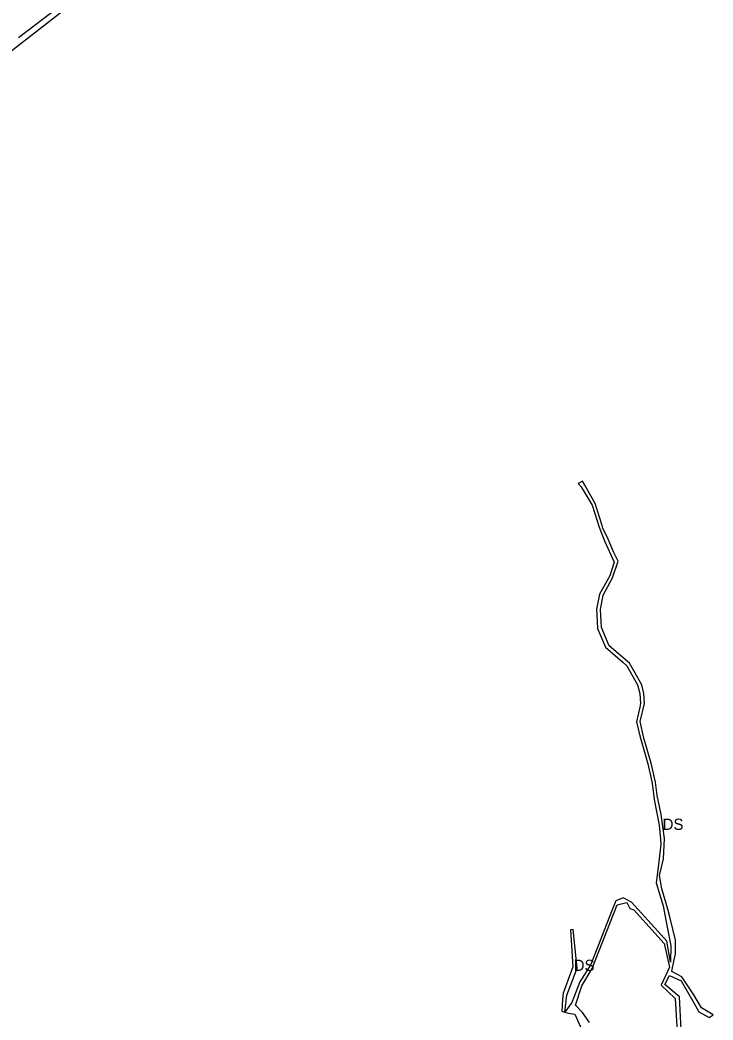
# Model space of a CAD drawing. Extents: x -477304 to -465641, y -1159113 to -1149285.
# Drawn here: x -474568 to -474013, y -1153742 to -1152941 of the extents above; entities that cross this region are included whole.
import ezdxf

# ---------------------------------------------------------------- set-up
doc = ezdxf.new("R2010")
doc.units = 0
doc.layers.add('35', color=7, linetype='Continuous')

msp = doc.modelspace()

# ---------------------------------------------------------------- linework, layer by layer
at = {"layer": '35'}
for p, q in [((-474117.21, -1153310.37), (-474120.55, -1153312.29)), ((-474120.55, -1153312.29), (-474118.33, -1153314.98)), ((-474118.33, -1153314.98), (-474109.34, -1153329.58)), ((-474115.45, -1153313.46), (-474117.21, -1153310.37)), ((-474107.08, -1153328.22), (-474115.45, -1153313.46)), ((-474109.34, -1153329.58), (-474103.95, -1153347.13)), ((-474101.48, -1153345.97), (-474107.08, -1153328.22)), ((-474103.95, -1153347.13), (-474099.47, -1153358.02)), ((-474100.84, -1153347.88), (-474101.48, -1153345.97)), ((-474096.77, -1153356.84), (-474100.84, -1153347.88)), ((-474092.37, -1153366.84), (-474096.77, -1153356.84)), ((-474088.52, -1153374.34), (-474092.37, -1153366.84)), ((-474103.66, -1153400.74), (-474106.05, -1153412.9)), ((-474102.89, -1153413.22), (-474100.52, -1153401.64)), ((-474106.05, -1153412.9), (-474105.79, -1153417.38)), ((-474101.96, -1153427.64), (-474102.89, -1153413.22)), ((-474085.02, -1153455.26), (-474081.66, -1153458.19)), ((-474067.44, -1153488.28), (-474067.98, -1153480.47)), ((-474070.9, -1153502.68), (-474067.44, -1153488.28)), ((-474068.12, -1153516.14), (-474070.9, -1153502.68)), ((-474062.31, -1153536.14), (-474068.12, -1153516.14)), ((-474058.76, -1153551.41), (-474062.31, -1153536.14)), ((-474061.5, -1153552.16), (-474059.87, -1153565.08)), ((-474052.35, -1153612.75), (-474051.54, -1153596.47)), ((-474055.51, -1153625.93), (-474052.35, -1153612.75)), ((-474053.57, -1153636.74), (-474055.51, -1153625.93)), ((-474090.58, -1153646.36), (-474093.46, -1153653.42)), ((-474079.23, -1153652.59), (-474076.22, -1153653.53)), ((-474054.16, -1153673.41), (-474078.06, -1153647.3)), ((-474124.63, -1153669.37), (-474126.72, -1153669.59)), ((-474126.72, -1153669.59), (-474125.01, -1153699.24)), ((-474049.73, -1153678.55), (-474054.16, -1153673.41)), ((-474046.8, -1153695.33), (-474049.73, -1153678.55)), ((-474044.05, -1153694.93), (-474042.79, -1153688.65)), ((-474125.01, -1153699.24), (-474131.86, -1153718.15)), ((-474047.55, -1153699.41), (-474054.24, -1153713.77)), ((-474051.31, -1153713.37), (-474047.41, -1153706.15)), ((-474047.41, -1153706.15), (-474038.28, -1153710.45)), ((-474119.24, -1153711.06), (-474125.83, -1153727.69)), ((-474054.24, -1153713.77), (-474042.87, -1153724.42)), ((-474039.59, -1153723.11), (-474051.31, -1153713.37)), ((-474038.28, -1153710.45), (-474028.15, -1153728)), ((-474133.27, -1153725.39), (-474133.86, -1153734.51)), ((-474132.57, -1153720.11), (-474133.27, -1153725.39)), ((-474131.86, -1153718.15), (-474132.57, -1153720.11)), ((-474042.87, -1153724.42), (-474040.46, -1153764.49)), ((-474037.51, -1153763.8), (-474039.59, -1153723.11)), ((-474021.87, -1153731.88), (-474028.13, -1153721.59)), ((-474125.83, -1153727.69), (-474131.38, -1153735.49)), ((-474117.25, -1153735.75), (-474122.83, -1153729.92)), ((-474028.15, -1153728), (-474023.99, -1153735.21)), ((-474012.71, -1153737.46), (-474021.87, -1153731.88)), ((-474133.86, -1153734.51), (-474131.38, -1153735.49)), ((-474131.38, -1153735.49), (-474130.55, -1153735.82)), ((-474130.55, -1153735.82), (-474128.42, -1153736.19)), ((-474128.42, -1153736.19), (-474123.38, -1153737.09)), ((-474123.38, -1153737.09), (-474117.93, -1153748.98)), ((-474111.71, -1153743.74), (-474117.25, -1153735.75)), ((-474023.99, -1153735.21), (-474015.76, -1153739.68)), ((-474015.76, -1153739.68), (-474012.71, -1153737.46))]:
    msp.add_line(p, q, dxfattribs=at)
for points in [[(-474597.04, -1152983.2), (-474505.55, -1152911.91), (-474507.82, -1152909.17), (-474536.44, -1152931.07), (-474568.74, -1152955.55)], [(-474099.47, -1153358.02), (-474091.82, -1153375.31), (-474095.39, -1153386.07), (-474103.66, -1153400.74)], [(-474100.52, -1153401.64), (-474093.21, -1153387.67), (-474088.52, -1153374.34)], [(-474105.79, -1153417.38), (-474105.14, -1153428.44), (-474098.81, -1153443.23), (-474085.02, -1153455.26)], [(-474079.53, -1153456.07), (-474095.77, -1153442.33), (-474101.96, -1153427.64)], [(-474081.66, -1153458.19), (-474073.06, -1153473.36), (-474071.25, -1153480.31)], [(-474067.98, -1153480.47), (-474069.71, -1153473.34), (-474079.53, -1153456.07)], [(-474071.25, -1153480.31), (-474070.84, -1153488.48), (-474071.42, -1153491.25)], [(-474071.42, -1153491.25), (-474073.88, -1153503.03), (-474071.34, -1153514.17)], [(-474071.34, -1153514.17), (-474064.78, -1153536.66), (-474061.5, -1153552.16)], [(-474051.54, -1153596.47), (-474054.33, -1153577.18), (-474057.31, -1153561.89), (-474058.76, -1153551.41)], [(-474059.87, -1153565.08), (-474055.76, -1153585.78), (-474054.75, -1153596.91)], [(-474054.75, -1153596.91), (-474054.39, -1153600.83), (-474056.05, -1153615.05), (-474058.32, -1153632), (-474052.56, -1153650.43), (-474050.37, -1153661.71)], [(-474047.09, -1153660.11), (-474048.83, -1153652.93), (-474053.57, -1153636.74)], [(-474078.06, -1153647.3), (-474084.75, -1153643.99), (-474090.58, -1153646.36)], [(-474122.83, -1153729.92), (-474117.81, -1153714.35), (-474109.44, -1153700.45), (-474089.52, -1153649.64)], [(-474089.52, -1153649.64), (-474081.68, -1153647.75), (-474079.23, -1153652.59)], [(-474093.46, -1153653.42), (-474110.62, -1153697.28), (-474119.24, -1153711.06)], [(-474076.22, -1153653.53), (-474051.72, -1153680.36), (-474047.55, -1153699.41)], [(-474042.79, -1153688.65), (-474042.79, -1153677.92), (-474047.09, -1153660.11)], [(-474131.38, -1153735.49), (-474129.72, -1153721.86), (-474121.59, -1153700.3), (-474124.63, -1153669.37)], [(-474050.37, -1153661.71), (-474046.37, -1153682.3), (-474046.8, -1153695.33)], [(-474045.63, -1153702.86), (-474045.3, -1153701.2), (-474044.05, -1153694.93)], [(-474028.13, -1153721.59), (-474037.68, -1153707.11), (-474045.63, -1153702.86)]]:
    msp.add_lwpolyline(points, dxfattribs=at)

# ---------------------------------------------------------------- texts
for p in [(-474053.07, -1153589.52), (-474124.28, -1153702.43)]:
    msp.add_text('DS', height=9, dxfattribs=at).set_placement(p)

doc.saveas('drawing.dxf')
